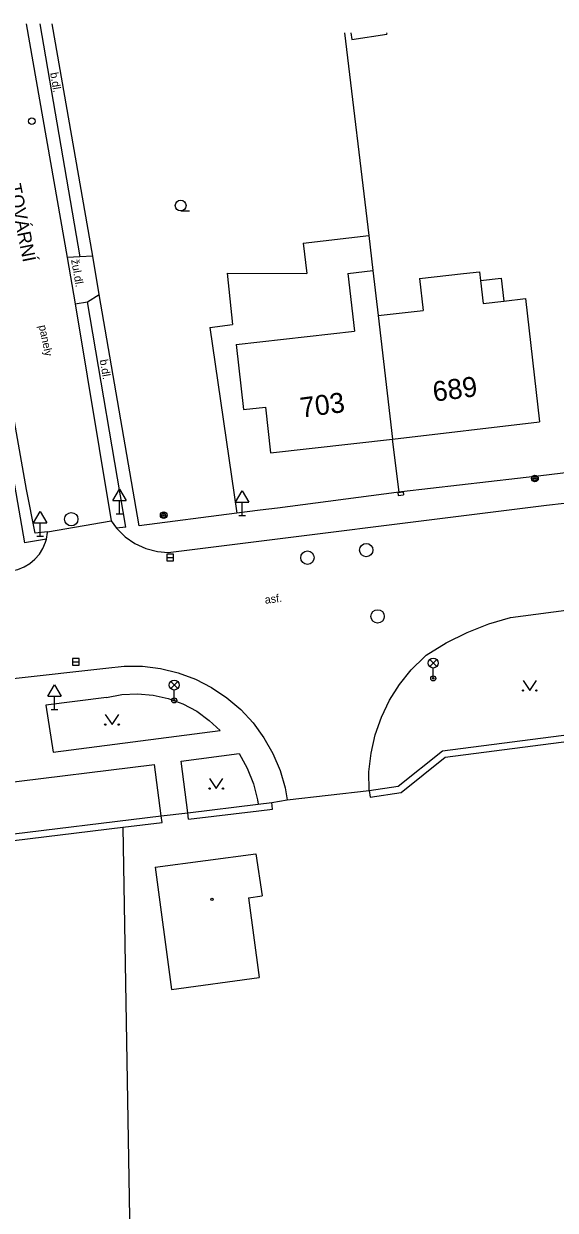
# Model space of a CAD drawing. Extents: x -640201 to -639641, y -1044739 to -1044317.
# Drawn here: x -639803.5 to -639763.7, y -1044406 to -1044317 of the extents above; entities that cross this region are included whole.
import ezdxf

# ---------------------------------------------------------------- set-up
doc = ezdxf.new("R2010")
doc.units = 0
for name, color, linetype in [('Budovy', 7, 'Continuous'), ('Ploty', 7, 'Continuous'), ('Popis povrchů', 7, 'Continuous'), ('Popis ulice', 7, 'Continuous'), ('Popis ČP_ ČE', 7, 'Continuous'), ('Pris-HUP', 7, 'Continuous'), ('Rozhraní ploch 1', 7, 'Continuous'), ('Rozhraní ploch 2', 7, 'Continuous'), ('Sloupy_označník', 7, 'Continuous'), ('Vstup na pozemky', 7, 'Continuous'), ('Znaky doprava', 7, 'Continuous'), ('Znaky kanalizace', 7, 'Continuous'), ('Znaky voda', 7, 'Continuous'), ('Značky doprava', 7, 'Continuous'), ('Značky KM', 7, 'Continuous'), ('Značky předmětů', 7, 'Continuous')]:
    doc.layers.add(name, color=color, linetype=linetype)

msp = doc.modelspace()

# ---------------------------------------------------------------- linework, layer by layer
at = {"layer": 'Budovy'}
for p, q in [((-639779.029, -1044317.715), (-639778.95, -1044318.23)), ((-639778.95, -1044318.23), (-639776.34, -1044317.81)), ((-639776.356, -1044317.715), (-639776.34, -1044317.81)), ((-639779.27, -1044335.77), (-639777.38, -1044335.55)), ((-639777.38, -1044335.55), (-639776.98, -1044338.91)), ((-639770.6, -1044335.76), (-639769.4, -1044335.63)), ((-639769.4, -1044335.63), (-639769.32, -1044336.29)), ((-639779.27, -1044335.77), (-639778.76, -1044340.08)), ((-639773.88, -1044336.14), (-639770.6, -1044335.76)), ((-639773.88, -1044336.14), (-639773.61, -1044338.53)), ((-639769.32, -1044336.29), (-639769.13, -1044338.01)), ((-639769.13, -1044338.01), (-639767.58, -1044337.84)), ((-639767.58, -1044337.84), (-639765.95, -1044337.65)), ((-639765.95, -1044337.65), (-639764.89, -1044346.89)), ((-639776.98, -1044338.91), (-639773.61, -1044338.53)), ((-639776.98, -1044338.91), (-639775.91, -1044348.19)), ((-639787.63, -1044341.08), (-639778.76, -1044340.08)), ((-639787.63, -1044341.08), (-639787.08, -1044345.97)), ((-639787.08, -1044345.97), (-639785.44, -1044345.78)), ((-639785.44, -1044345.78), (-639785.05, -1044349.22)), ((-639775.91, -1044348.19), (-639764.89, -1044346.89)), ((-639785.05, -1044349.22), (-639775.91, -1044348.19)), ((-639793.69, -1044380.28), (-639786.15, -1044379.28)), ((-639786.15, -1044379.28), (-639785.68, -1044382.43)), ((-639793.69, -1044380.28), (-639792.47, -1044389.44)), ((-639786.7, -1044382.57), (-639785.68, -1044382.43)), ((-639786.7, -1044382.57), (-639785.91, -1044388.54)), ((-639792.47, -1044389.44), (-639785.91, -1044388.54))]:
    msp.add_line(p, q, dxfattribs=at)
at = {"layer": 'Ploty'}
for p, q in [((-639798.38, -1044334.46), (-639801.418, -1044317.039)), ((-639794.89, -1044354.68), (-639797.9, -1044337.35)), ((-639775.42, -1044352.16), (-639775.91, -1044348.19)), ((-639764.37, -1044350.88), (-639775.233, -1044352.138)), ((-639775.624, -1044352.187), (-639784.54, -1044353.35)), ((-639775.42, -1044352.16), (-639775.624, -1044352.187)), ((-639775.233, -1044352.138), (-639775.42, -1044352.16)), ((-639787.577, -1044353.741), (-639794.89, -1044354.68)), ((-639785.829, -1044353.516), (-639787.577, -1044353.741)), ((-639772.18, -1044371.56), (-639745.24, -1044368.05)), ((-639771.977, -1044372.038), (-639745.178, -1044368.546)), ((-639775.48, -1044374.21), (-639772.18, -1044371.56)), ((-639775.274, -1044374.686), (-639771.977, -1044372.038)), ((-639777.67, -1044374.52), (-639775.48, -1044374.21)), ((-639777.67, -1044374.52), (-639777.6, -1044375.015)), ((-639777.6, -1044375.015), (-639775.274, -1044374.686)), ((-639791.253, -1044376.191), (-639785.978, -1044375.553)), ((-639785.978, -1044375.553), (-639784.96, -1044375.43)), ((-639784.9, -1044375.926), (-639784.96, -1044375.43)), ((-639828.74, -1044380.764), (-639793.245, -1044376.431)), ((-639793.184, -1044376.927), (-639793.245, -1044376.431)), ((-639791.193, -1044376.687), (-639791.253, -1044376.191)), ((-639791.193, -1044376.687), (-639785.918, -1044376.049)), ((-639785.918, -1044376.049), (-639784.9, -1044375.926)), ((-639828.889, -1044381.286), (-639796.111, -1044377.284)), ((-639796.111, -1044377.284), (-639793.184, -1044376.927))]:
    msp.add_line(p, q, dxfattribs=at)
at = {"layer": 'Pris-HUP'}
for p, q in [((-639775.515, -1044352.193), (-639775.125, -1044352.133)), ((-639775.515, -1044352.193), (-639775.48, -1044352.42)), ((-639775.48, -1044352.42), (-639775.09, -1044352.36)), ((-639775.125, -1044352.133), (-639775.09, -1044352.36))]:
    msp.add_line(p, q, dxfattribs=at)
at = {"layer": 'Rozhraní ploch 1'}
for p, q in [((-639810.26, -1044317.19), (-639803.48, -1044355.97)), ((-639803.35, -1044351.96), (-639809.45, -1044317.36)), ((-639803.352, -1044317.039), (-639800.3, -1044334.57)), ((-639802.351, -1044317.039), (-639799.343, -1044334.515)), ((-639799.343, -1044334.515), (-639800.3, -1044334.57)), ((-639800.3, -1044334.57), (-639799.69, -1044338.05)), ((-639799.69, -1044338.05), (-639798.76, -1044337.9)), ((-639799.69, -1044338.05), (-639797, -1044354.3)), ((-639795.89, -1044354.78), (-639798.76, -1044337.9)), ((-639764.37, -1044353.14), (-639743.26, -1044350.71)), ((-639802.68, -1044355.24), (-639803.35, -1044351.96)), ((-639792.73, -1044356.68), (-639764.37, -1044353.14)), ((-639797, -1044354.3), (-639796.6, -1044354.851)), ((-639801.76, -1044355.13), (-639802.68, -1044355.24)), ((-639795.89, -1044354.78), (-639796.6, -1044354.851)), ((-639801.845, -1044355.684), (-639803.48, -1044355.97)), ((-639767.07, -1044361.56), (-639761.95, -1044360.89)), ((-639804.33, -1044366.12), (-639797.39, -1044365.36)), ((-639801.34, -1044371.65), (-639788.84, -1044370.04)), ((-639791.76, -1044372.32), (-639787.4, -1044371.76)), ((-639809.37, -1044374.49), (-639793.75, -1044372.57)), ((-639793.245, -1044376.431), (-639793.75, -1044372.57)), ((-639791.253, -1044376.191), (-639791.76, -1044372.32))]:
    msp.add_line(p, q, dxfattribs=at)
for points in [[(-639801.845, -1044355.684), (-639801.763, -1044355.175), (-639801.76, -1044355.13)], [(-639796.6, -1044354.851), (-639795.95, -1044355.5), (-639795.222, -1044356.006), (-639794.402, -1044356.383), (-639793.529, -1044356.61), (-639792.73, -1044356.68)], [(-639804.48, -1044358.06), (-639803.989, -1044357.951), (-639803.522, -1044357.766), (-639803.09, -1044357.509), (-639802.703, -1044357.187), (-639802.373, -1044356.808), (-639802.107, -1044356.381), (-639801.912, -1044355.918), (-639801.845, -1044355.684)], [(-639773.38, -1044364.39), (-639771.892, -1044363.463), (-639770.326, -1044362.676), (-639768.694, -1044362.035), (-639767.07, -1044361.56)], [(-639774.507, -1044365.485), (-639773.507, -1044364.5), (-639773.38, -1044364.39)], [(-639797.39, -1044365.36), (-639796.029, -1044365.208), (-639794.659, -1044365.215), (-639793.3, -1044365.382), (-639791.97, -1044365.707), (-639790.686, -1044366.184), (-639789.466, -1044366.807), (-639788.328, -1044367.568)], [(-639777.67, -1044374.52), (-639777.677, -1044373.116), (-639777.525, -1044371.721), (-639777.214, -1044370.352), (-639776.75, -1044369.027), (-639776.139, -1044367.764), (-639775.388, -1044366.578), (-639774.507, -1044365.485)], [(-639797.34, -1044367.56), (-639801.88, -1044368.13), (-639801.34, -1044371.65)], [(-639797.34, -1044367.56), (-639796.191, -1044367.338), (-639795.023, -1044367.274), (-639793.857, -1044367.371), (-639792.715, -1044367.625), (-639791.619, -1044368.033), (-639790.588, -1044368.586), (-639789.642, -1044369.274), (-639788.84, -1044370.04)], [(-639788.328, -1044367.568), (-639787.286, -1044368.457), (-639786.355, -1044369.461), (-639785.547, -1044370.567), (-639784.873, -1044371.76), (-639784.343, -1044373.022), (-639783.964, -1044374.338), (-639783.8, -1044375.22)], [(-639787.4, -1044371.76), (-639786.797, -1044372.858), (-639786.338, -1044374.024), (-639786.031, -1044375.238), (-639785.978, -1044375.553)]]:
    msp.add_lwpolyline(points, dxfattribs=at)
at = {"layer": 'Rozhraní ploch 2'}
for p, q in [((-639779.504, -1044317.715), (-639777.7, -1044332.91)), ((-639782.61, -1044333.49), (-639777.7, -1044332.91)), ((-639777.7, -1044332.91), (-639777.38, -1044335.55)), ((-639782.61, -1044333.49), (-639782.34, -1044335.77)), ((-639798.38, -1044334.46), (-639799.343, -1044334.515)), ((-639788.31, -1044335.73), (-639787.91, -1044339.59)), ((-639788.31, -1044335.73), (-639782.34, -1044335.77)), ((-639769.32, -1044336.29), (-639767.77, -1044336.12)), ((-639767.77, -1044336.12), (-639767.58, -1044337.84)), ((-639798.76, -1044337.9), (-639797.9, -1044337.35)), ((-639789.59, -1044339.82), (-639787.91, -1044339.59)), ((-639789.59, -1044339.82), (-639787.577, -1044353.741)), ((-639801.76, -1044355.13), (-639797, -1044354.3)), ((-639796.111, -1044377.284), (-639795.53, -1044411.73))]:
    msp.add_line(p, q, dxfattribs=at)
at = {"layer": 'Sloupy_označník'}
for centre, radius in [((-639765.24, -1044351.14), 0.25), ((-639765.24, -1044351.14), 0.158), ((-639765.24, -1044351.14), 0.05), ((-639793.06, -1044353.89), 0.25), ((-639793.06, -1044353.89), 0.158), ((-639793.06, -1044353.89), 0.05)]:
    msp.add_circle(centre, radius, dxfattribs=at)
at = {"layer": 'Vstup na pozemky'}
for p, q in [((-639797.9, -1044337.35), (-639798.38, -1044334.46)), ((-639760.11, -1044350.38), (-639764.37, -1044350.88)), ((-639784.54, -1044353.35), (-639785.829, -1044353.516)), ((-639783.8, -1044375.22), (-639777.67, -1044374.52)), ((-639784.96, -1044375.43), (-639783.8, -1044375.22)), ((-639793.245, -1044376.431), (-639791.253, -1044376.191))]:
    msp.add_line(p, q, dxfattribs=at)
at = {"layer": 'Znaky doprava'}
for p, q in [((-639773.125, -1044364.705), (-639772.595, -1044365.235)), ((-639773.125, -1044365.235), (-639772.595, -1044364.705)), ((-639772.86, -1044366.12), (-639772.86, -1044365.345)), ((-639792.535, -1044366.355), (-639792.005, -1044366.885)), ((-639792.535, -1044366.885), (-639792.005, -1044366.355)), ((-639792.27, -1044367.77), (-639792.27, -1044366.995))]:
    msp.add_line(p, q, dxfattribs=at)
for centre, radius in [((-639772.86, -1044364.97), 0.375), ((-639792.27, -1044366.62), 0.375), ((-639772.86, -1044366.12), 0.19), ((-639772.86, -1044366.12), 0.05), ((-639792.27, -1044367.77), 0.19), ((-639792.27, -1044367.77), 0.05)]:
    msp.add_circle(centre, radius, dxfattribs=at)
at = {"layer": 'Znaky kanalizace'}
for p, q in [((-639792.83, -1044357.06), (-639792.33, -1044357.06)), ((-639799.89, -1044364.89), (-639799.39, -1044364.89))]:
    msp.add_line(p, q, dxfattribs=at)
for points in [[(-639792.83, -1044357.31), (-639792.33, -1044357.31), (-639792.33, -1044356.81), (-639792.83, -1044356.81)], [(-639799.89, -1044365.14), (-639799.39, -1044365.14), (-639799.39, -1044364.64), (-639799.89, -1044364.64)]]:
    msp.add_lwpolyline(points, close=True, dxfattribs=at)
for centre in [(-639799.98, -1044354.19), (-639777.88, -1044356.5), (-639782.29, -1044357.07), (-639777.03, -1044361.47)]:
    msp.add_circle(centre, 0.5, dxfattribs=at)
at = {"layer": 'Znaky voda'}
msp.add_circle((-639802.94, -1044324.34), 0.25, dxfattribs=at)
at = {"layer": 'Značky doprava'}
for p, q in [((-639796.88, -1044352.78), (-639796.38, -1044351.93)), ((-639796.38, -1044351.93), (-639795.88, -1044352.78)), ((-639787.68, -1044352.9), (-639787.18, -1044352.05)), ((-639787.18, -1044352.05), (-639786.68, -1044352.9)), ((-639796.88, -1044352.78), (-639795.88, -1044352.78)), ((-639796.38, -1044353.78), (-639796.38, -1044352.78)), ((-639787.68, -1044352.9), (-639786.68, -1044352.9)), ((-639787.18, -1044353.9), (-639787.18, -1044352.9)), ((-639802.81, -1044354.45), (-639802.31, -1044353.6)), ((-639802.31, -1044353.6), (-639801.81, -1044354.45)), ((-639796.63, -1044353.78), (-639796.13, -1044353.78)), ((-639787.43, -1044353.9), (-639786.93, -1044353.9)), ((-639802.81, -1044354.45), (-639801.81, -1044354.45)), ((-639802.31, -1044355.45), (-639802.31, -1044354.45)), ((-639802.56, -1044355.45), (-639802.06, -1044355.45)), ((-639801.73, -1044367.46), (-639801.23, -1044366.61)), ((-639801.23, -1044366.61), (-639800.73, -1044367.46)), ((-639801.73, -1044367.46), (-639800.73, -1044367.46)), ((-639801.23, -1044368.46), (-639801.23, -1044367.46)), ((-639801.48, -1044368.46), (-639800.98, -1044368.46))]:
    msp.add_line(p, q, dxfattribs=at)
at = {"layer": 'Značky KM'}
for p, q in [((-639791.784, -1044331.078), (-639791.134, -1044331.075)), ((-639766.131, -1044366.28), (-639765.631, -1044367.03)), ((-639765.631, -1044367.03), (-639765.131, -1044366.28)), ((-639797.432, -1044368.833), (-639796.932, -1044369.583)), ((-639796.932, -1044369.583), (-639796.432, -1044368.833)), ((-639789.618, -1044373.635), (-639789.118, -1044374.385)), ((-639789.118, -1044374.385), (-639788.618, -1044373.635))]:
    msp.add_line(p, q, dxfattribs=at)
for centre, radius in [((-639791.784, -1044330.675), 0.403), ((-639766.131, -1044367.03), 0.05), ((-639765.131, -1044367.03), 0.05), ((-639797.432, -1044369.583), 0.05), ((-639796.432, -1044369.583), 0.05), ((-639789.618, -1044374.385), 0.05), ((-639788.618, -1044374.385), 0.05)]:
    msp.add_circle(centre, radius, dxfattribs=at)
at = {"layer": 'Značky předmětů'}
msp.add_circle((-639789.45, -1044382.68), 0.0875, dxfattribs=at)

# ---------------------------------------------------------------- texts
at = {"layer": 'Popis povrchů'}
for s, rotation, p in [('b.dl.', 279.76764, (-639801.572, -1044320.735)), ('žul.dl.', 279.94222, (-639799.999, -1044334.757)), ('panely', 281.66282, (-639802.418, -1044339.689)), ('b.dl.', 279.64936, (-639797.851, -1044342.254)), ('asf.', 7.11507, (-639785.451, -1044360.53))]:
    msp.add_text(s, height=0.6, rotation=rotation, dxfattribs=at).set_placement(p)
at = {"layer": 'Popis ulice'}
msp.add_text('TOVÁRNÍ', height=1, rotation=281.32167, dxfattribs=at).set_placement((-639804.75, -1044329.142))
at = {"layer": 'Popis ČP_ ČE'}
for s, p in [('689', (-639772.803, -1044345.382)), ('703', (-639782.736, -1044346.577))]:
    msp.add_text(s, height=1.5, rotation=7.48966, dxfattribs=at).set_placement(p)

doc.saveas('drawing.dxf')
